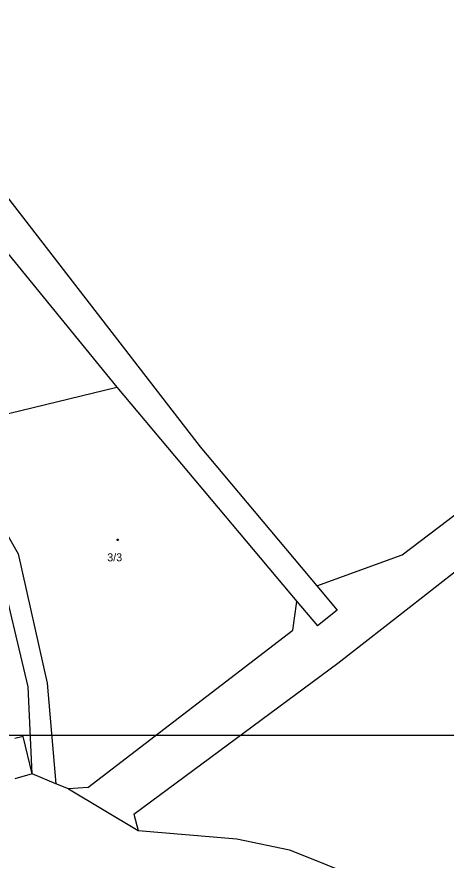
# Model space of a CAD drawing. Extents: x -802857 to -799647, y -1020285 to -1015884.
# Drawn here: x -801316.9 to -801225.7, y -1017640.2 to -1017461.1 of the extents above; entities that cross this region are included whole.
import ezdxf

# ---------------------------------------------------------------- set-up
doc = ezdxf.new("R2010")
doc.units = 0
for name, color, linetype in [('Default', 7, 'Continuous'), ('KN_HRANICE', 7, 'Continuous'), ('KN_KULTURY', 7, 'Continuous'), ('KN_PARCELY', 7, 'Continuous'), ('LEGENDA', 7, 'Continuous')]:
    doc.layers.add(name, color=color, linetype=linetype)

# ---------------------------------------------------------------- blocks, each defined once
blk = doc.blocks.new('NAHRADNI_SYMBOL')
at = {"layer": 'Default'}
blk.add_lwpolyline([(0.09, 0.15), (0.18, 0), (0.09, -0.15), (-0.09, -0.15), (-0.18, 0), (-0.09, 0.15), (0.09, 0.15)], dxfattribs=at)

msp = doc.modelspace()

# ---------------------------------------------------------------- linework, layer by layer
at = {"layer": 'KN_HRANICE'}
for p, q in [((-801235.08, -1017575.37), (-801095.04, -1017469.02)), ((-801324.28, -1017492.5), (-801277.94, -1017552.4)), ((-801330.52, -1017497.1), (-801295.7, -1017539.76)), ((-801337.12, -1017549.87), (-801295.7, -1017539.76)), ((-801295.7, -1017539.76), (-801257.41, -1017585.32)), ((-801277.94, -1017552.4), (-801253.19, -1017581.98)), ((-801324.97, -1017560.63), (-801316.63, -1017575.17)), ((-801232.93, -1017586.06), (-801214.32, -1017571.47)), ((-801316.63, -1017575.17), (-801310.44, -1017602.62)), ((-801314.53, -1017603.45), (-801320.87, -1017576.78)), ((-801253.19, -1017581.98), (-801235.08, -1017575.37)), ((-801253.19, -1017581.98), (-801248.88, -1017587.13)), ((-801258.27, -1017591.39), (-801257.41, -1017585.32)), ((-801257.41, -1017585.32), (-801253, -1017590.46)), ((-801248.88, -1017587.13), (-801253, -1017590.46)), ((-801248.69, -1017598.39), (-801232.93, -1017586.06)), ((-801301.82, -1017624.81), (-801258.27, -1017591.39)), ((-801292.02, -1017630.5), (-801248.69, -1017598.39)), ((-801313.67, -1017621.93), (-801314.53, -1017603.45)), ((-801310.44, -1017602.62), (-801308.63, -1017624.01)), ((-801315.54, -1017613.96), (-801317.34, -1017614.38)), ((-801313.67, -1017621.93), (-801315.54, -1017613.96)), ((-801313.67, -1017621.93), (-801317.37, -1017622.97)), ((-801308.63, -1017624.01), (-801313.67, -1017621.93)), ((-801305.91, -1017625.13), (-801308.63, -1017624.01)), ((-801301.82, -1017624.81), (-801305.91, -1017625.13)), ((-801305.91, -1017625.13), (-801291.14, -1017633.93)), ((-801292.02, -1017630.5), (-801291.14, -1017633.93)), ((-801291.14, -1017633.93), (-801270.14, -1017635.69)), ((-801270.14, -1017635.69), (-801258.97, -1017638.08)), ((-801258.97, -1017638.08), (-801218.75, -1017654.12))]:
    msp.add_line(p, q, dxfattribs=at)
at = {"layer": 'LEGENDA'}
msp.add_lwpolyline([(-801703.84, -1017613.71), (-800862.84, -1017613.71), (-800862.84, -1017019.71), (-801703.84, -1017019.71)], close=True, dxfattribs=at)

# ---------------------------------------------------------------- block references
at = {"layer": 'KN_KULTURY'}
msp.add_blockref('NAHRADNI_SYMBOL', (-801295.5, -1017572.21), dxfattribs=at)

# ---------------------------------------------------------------- texts
at = {"layer": 'KN_PARCELY'}
msp.add_text('3/3', height=1.7, dxfattribs=at).set_placement((-801297.7, -1017576.76))

doc.saveas('drawing.dxf')
